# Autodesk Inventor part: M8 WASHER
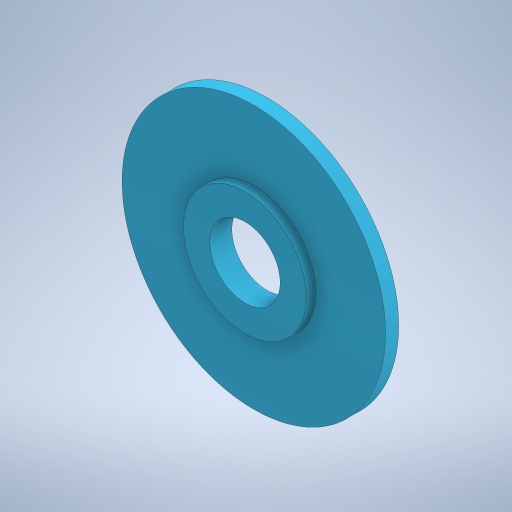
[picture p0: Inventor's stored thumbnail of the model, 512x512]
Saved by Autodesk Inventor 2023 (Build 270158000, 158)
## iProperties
Created: 2025-07
Part Number: M8 WASHER
Material: Generic
Document SubType Name: Modeling
Designer: erjon
Density: 1 g/cm^3
Appearance: Default
Author: erjon
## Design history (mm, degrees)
feature "Base1"
body "Solid1"
